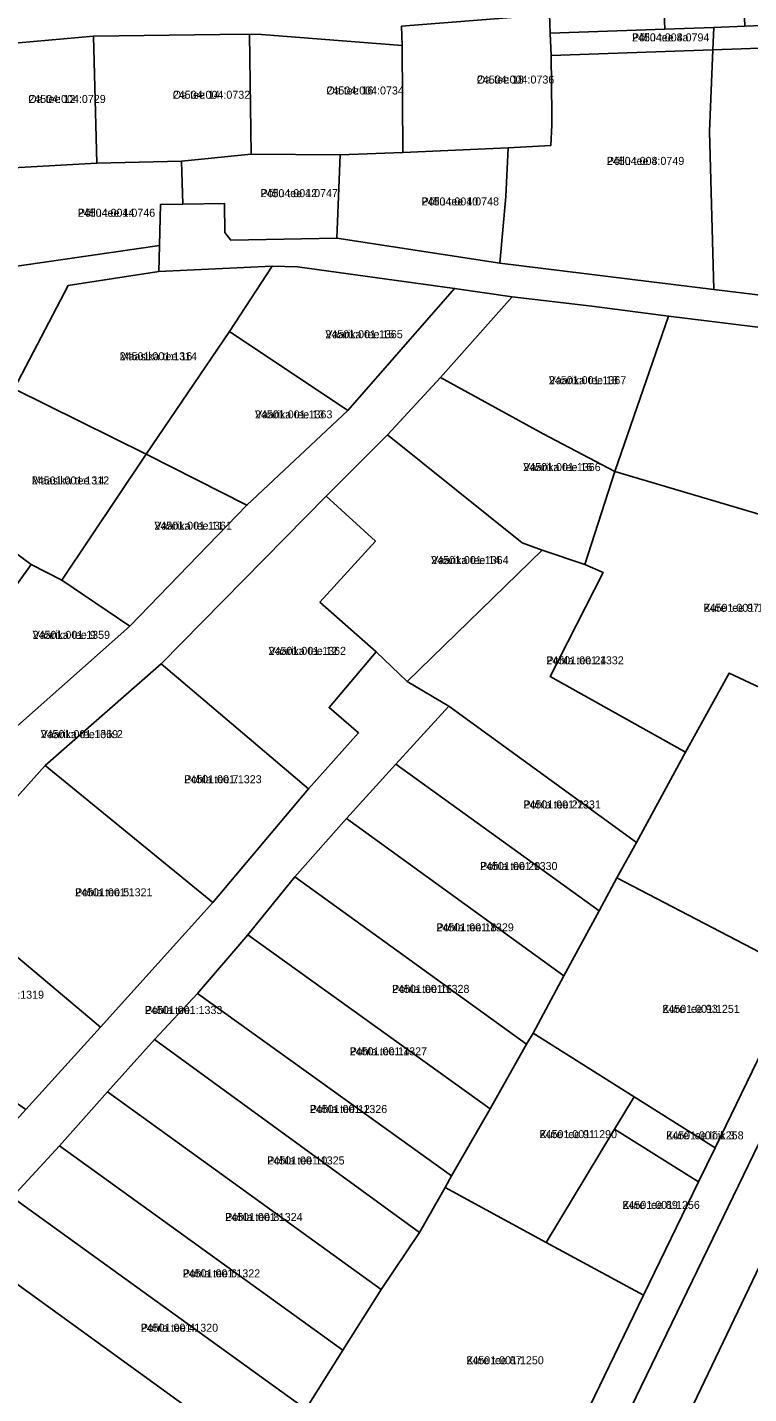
# Model space of a CAD drawing. Extents: x 551291 to 575799, y 6581704 to 6610137.
# Drawn here: x 559243.4 to 559378.6, y 6593957.3 to 6594213.3 of the extents above; entities that cross this region are included whole.
import ezdxf

# ---------------------------------------------------------------- set-up
doc = ezdxf.new("R2010")
doc.units = 0
for name, color, linetype in [('L_AADRESS', 7, 'Continuous'), ('PIIR', 7, 'Continuous'), ('TUNNUS', 7, 'Continuous')]:
    doc.layers.add(name, color=color, linetype=linetype)

msp = doc.modelspace()

# ---------------------------------------------------------------- linework, layer by layer
at = {"layer": 'PIIR'}
for points in [[(559360.98, 6594319.58), (559370.22, 6594319.03), (559371.34, 6594293.74), (559372.28, 6594272.9), (559373.15, 6594252.95), (559374, 6594233.72), (559374.56, 6594221.12), (559377.53, 6594221.22), (559377.81, 6594213.53), (559372.03, 6594213.32), (559362.82, 6594213), (559362.55, 6594220.7), (559365.37, 6594220.81), (559364.01, 6594251.33), (559363.11, 6594271.73), (559362.14, 6594293.49)], [(559339.71, 6594249.91), (559364.01, 6594251.33), (559365.37, 6594220.81), (559362.55, 6594220.7), (559362.82, 6594213), (559341.38, 6594212.26), (559341.23, 6594215.7)], [(559313.5, 6594213.53), (559341.23, 6594215.7), (559341.38, 6594212.26), (559341.57, 6594208.06), (559341.64, 6594197), (559341.67, 6594195.06), (559341.48, 6594191.17), (559333.49, 6594190.74), (559313.76, 6594189.88), (559313.6, 6594209.89)], [(559341.38, 6594212.26), (559362.82, 6594213), (559372.03, 6594213.32), (559371.86, 6594209.12), (559341.57, 6594208.06)], [(559372.03, 6594213.32), (559377.81, 6594213.53), (559390.9, 6594214.04), (559391.34, 6594209.8), (559371.86, 6594209.12)], [(559230.42, 6594209.43), (559255.79, 6594211.66), (559256.4, 6594187.84), (559240.77, 6594186.97), (559231.8, 6594186.64)], [(559255.79, 6594211.66), (559279.49, 6594211.99), (559285.04, 6594212.04), (559285.36, 6594189.56), (559272.3, 6594188.24), (559256.4, 6594187.84)], [(559285.04, 6594212.04), (559287.3, 6594211.98), (559313.6, 6594209.89), (559313.76, 6594189.88), (559302, 6594189.44), (559285.36, 6594189.56)], [(559341.57, 6594208.06), (559371.86, 6594209.12), (559371.19, 6594193.81), (559372.02, 6594164.2), (559331.93, 6594169.16), (559333.08, 6594181.65), (559333.49, 6594190.74), (559341.48, 6594191.17), (559341.67, 6594195.06), (559341.64, 6594197)], [(559371.86, 6594209.12), (559391.34, 6594209.8), (559396.5, 6594159.81), (559384.32, 6594162.68), (559372.02, 6594164.2), (559371.19, 6594193.81)], [(559272.3, 6594188.24), (559285.36, 6594189.56), (559302, 6594189.44), (559301.37, 6594173.82), (559281.5, 6594173.45), (559280.41, 6594174.89), (559280.31, 6594180.32), (559272.53, 6594180.18)], [(559302, 6594189.44), (559313.76, 6594189.88), (559333.49, 6594190.74), (559333.08, 6594181.65), (559331.93, 6594169.16), (559301.37, 6594173.82)], [(559240.77, 6594186.97), (559256.4, 6594187.84), (559272.3, 6594188.24), (559272.53, 6594180.18), (559268.32, 6594180.11), (559268.14, 6594172.42), (559233.63, 6594167.43)], [(559141.77, 6594022.54), (559133.39, 6594026.69), (559151.28, 6594046.35), (559186.46, 6594085.05), (559197.1, 6594096.92), (559217.09, 6594129.91), (559229.13, 6594155.42), (559233.63, 6594167.43), (559268.14, 6594172.42), (559268.03, 6594167.56), (559251.07, 6594164.93), (559240.92, 6594145.6), (559225.55, 6594126.37), (559210.74, 6594101.87), (559204.3, 6594091.2), (559175.94, 6594060.13)], [(559240.92, 6594145.6), (559251.07, 6594164.93), (559268.03, 6594167.56), (559289.26, 6594168.57), (559281.29, 6594156.31), (559265.69, 6594133.31)], [(559281.29, 6594156.31), (559289.26, 6594168.57), (559294.01, 6594168.44), (559323.46, 6594164.39), (559303.46, 6594141.55)], [(559176.16, 6593995.86), (559169.11, 6594001.47), (559187.62, 6594022.9), (559201.71, 6594038.84), (559219.93, 6594058.81), (559236.88, 6594077.64), (559240.46, 6594081.45), (559262.6, 6594101.09), (559284.55, 6594123.76), (559303.46, 6594141.55), (559323.46, 6594164.39), (559334.22, 6594162.81), (559320.79, 6594147.7), (559310.88, 6594136.93), (559299.37, 6594125.45), (559268.46, 6594094.04), (559246.72, 6594074.98), (559226.13, 6594052.02), (559209.61, 6594033.82), (559191.25, 6594013.56)], [(559320.79, 6594147.7), (559334.22, 6594162.81), (559349.19, 6594161.04), (559363.55, 6594159.21), (559353.48, 6594130.09), (559340.07, 6594137.15)], [(559353.48, 6594130.09), (559363.55, 6594159.21), (559383.32, 6594156.78), (559406.79, 6594151.23), (559396.8, 6594124.4), (559395.42, 6594117.64)], [(559265.69, 6594133.31), (559281.29, 6594156.31), (559303.46, 6594141.55), (559284.55, 6594123.76)], [(559310.88, 6594136.93), (559320.79, 6594147.7), (559340.07, 6594137.15), (559353.48, 6594130.09), (559347.84, 6594112.65), (559339.89, 6594115.33), (559336.09, 6594116.74)], [(559225.55, 6594126.37), (559240.92, 6594145.6), (559265.69, 6594133.31), (559249.84, 6594109.71), (559244.12, 6594112.66)], [(559171.21, 6593753.59), (559201.87, 6593775.34), (559209.55, 6593780.73), (559246.25, 6593806.94), (559271.02, 6593824.58), (559293.51, 6593840.52), (559316.24, 6593887.55), (559335.18, 6593926.77), (559358.82, 6593975.74), (559369.18, 6593996.97), (559372.27, 6594003.33), (559388.13, 6594036.07), (559408, 6594077.05), (559411.94, 6594085.21), (559438.12, 6594139.38), (559444.58, 6594136.67), (559299.06, 6593836.09), (559146.17, 6593723.99), (559138.1, 6593729.93)], [(559308.63, 6594117.03), (559299.37, 6594125.45), (559310.88, 6594136.93), (559336.09, 6594116.74), (559339.89, 6594115.33), (559314.57, 6594090.74), (559308.74, 6594096.28), (559298.23, 6594105.61)], [(559249.84, 6594109.71), (559265.69, 6594133.31), (559284.55, 6594123.76), (559262.6, 6594101.09)], [(559347.84, 6594112.65), (559353.48, 6594130.09), (559395.42, 6594117.64), (559390.93, 6594094.77), (559387.35, 6594086.49), (559374.9, 6594092.31), (559366.72, 6594077.52), (559341.33, 6594091.68), (559351.27, 6594111.15)], [(559210.74, 6594101.87), (559225.55, 6594126.37), (559244.12, 6594112.66), (559226.18, 6594087.74)], [(559296.09, 6594070.61), (559268.46, 6594094.04), (559299.37, 6594125.45), (559308.63, 6594117.03), (559298.23, 6594105.61), (559308.74, 6594096.28), (559299.94, 6594085.85), (559305.45, 6594081.11)], [(559322.35, 6594086.1), (559314.57, 6594090.74), (559339.89, 6594115.33), (559347.84, 6594112.65), (559351.27, 6594111.15), (559341.33, 6594091.68), (559366.72, 6594077.52), (559357.52, 6594060.57)], [(559236.88, 6594077.64), (559226.18, 6594087.74), (559244.12, 6594112.66), (559249.84, 6594109.71), (559262.6, 6594101.09), (559240.46, 6594081.45)], [(559216.33, 6593968.06), (559208.51, 6593972.88), (559228.04, 6593993.97), (559243.12, 6594010.55), (559257.11, 6594025.97), (559278.13, 6594049.31), (559296.09, 6594070.61), (559305.45, 6594081.11), (559299.94, 6594085.85), (559308.74, 6594096.28), (559314.57, 6594090.74), (559322.35, 6594086.1), (559312.44, 6594075.24), (559303.19, 6594065.05), (559293.53, 6594054.14), (559284.72, 6594043.28), (559275.28, 6594032.28), (559267.25, 6594023.67), (559258.44, 6594013.84), (559249.43, 6594003.75), (559240.57, 6593994.11), (559231.85, 6593984.75)], [(559278.13, 6594049.31), (559246.72, 6594074.98), (559268.46, 6594094.04), (559296.09, 6594070.61)], [(559366.72, 6594077.52), (559374.9, 6594092.31), (559387.35, 6594086.49), (559408, 6594077.05), (559388.13, 6594036.07), (559353.88, 6594053.95), (559357.52, 6594060.57)], [(559350.52, 6594047.77), (559312.44, 6594075.24), (559322.35, 6594086.1), (559357.52, 6594060.57), (559353.88, 6594053.95)], [(559257.11, 6594025.97), (559226.13, 6594052.02), (559246.72, 6594074.98), (559278.13, 6594049.31)], [(559343.93, 6594035.56), (559303.19, 6594065.05), (559312.44, 6594075.24), (559350.52, 6594047.77)], [(559336.9, 6594022.76), (559293.53, 6594054.14), (559303.19, 6594065.05), (559343.93, 6594035.56), (559338.17, 6594024.81)], [(559330.1, 6594010.63), (559284.72, 6594043.28), (559293.53, 6594054.14), (559336.9, 6594022.76)], [(559357.07, 6594012.9), (559338.17, 6594024.81), (559343.93, 6594035.56), (559350.52, 6594047.77), (559353.88, 6594053.95), (559388.13, 6594036.07), (559372.27, 6594003.33)], [(559243.12, 6594010.55), (559209.61, 6594033.82), (559226.13, 6594052.02), (559257.11, 6594025.97)], [(559322.9, 6593998.07), (559275.28, 6594032.28), (559284.72, 6594043.28), (559330.1, 6594010.63)], [(559316.9, 6593987.46), (559267.25, 6594023.67), (559275.28, 6594032.28), (559322.9, 6593998.07), (559321.68, 6593995.94)], [(559309.71, 6593976.78), (559258.44, 6594013.84), (559267.25, 6594023.67), (559316.9, 6593987.46)], [(559340.62, 6593985.59), (559321.68, 6593995.94), (559322.9, 6593998.07), (559330.1, 6594010.63), (559336.9, 6594022.76), (559338.17, 6594024.81), (559357.07, 6594012.9), (559353.42, 6594006.86)], [(559302.54, 6593965.43), (559249.43, 6594003.75), (559258.44, 6594013.84), (559309.71, 6593976.78)], [(559369.18, 6593996.97), (559353.42, 6594006.86), (559357.07, 6594012.9), (559372.27, 6594003.33)], [(559358.82, 6593975.74), (559340.62, 6593985.59), (559353.42, 6594006.86), (559369.18, 6593996.97)], [(559295.57, 6593954.38), (559240.57, 6593994.11), (559249.43, 6594003.75), (559302.54, 6593965.43)], [(559329.03, 6593930.04), (559292.49, 6593949.23), (559295.57, 6593954.38), (559302.54, 6593965.43), (559309.71, 6593976.78), (559316.9, 6593987.46), (559321.68, 6593995.94), (559340.62, 6593985.59), (559358.82, 6593975.74), (559335.18, 6593926.77)], [(559288.65, 6593943.64), (559231.85, 6593984.75), (559240.57, 6593994.11), (559295.57, 6593954.38), (559292.49, 6593949.23)], [(559356.41, 6593930.63), (559383.45, 6593987.17), (559409.15, 6593975.66), (559399.46, 6593951.77), (559396.72, 6593952.85), (559384.6, 6593929.42), (559377.88, 6593931.06), (559371.31, 6593922.02)], [(559216.48, 6593966.93), (559216.33, 6593968.06), (559231.85, 6593984.75), (559288.65, 6593943.64), (559277.28, 6593925.6)]]:
    msp.add_lwpolyline(points, close=True, dxfattribs=at)
for points in [[(559313.5, 6594213.53), (559313.6, 6594209.89), (559287.3, 6594211.98), (559285.04, 6594212.04), (559279.49, 6594211.99), (559255.79, 6594211.66), (559230.42, 6594209.43), (559203.44, 6594209.05), (559177.17, 6594208.65), (559147.66, 6594208.18), (559120.38, 6594207.76), (559108.39, 6594207.58), (559108.36, 6594209.68), (559108.17, 6594222.79)], [(558177.52, 6592770.55), (558170.99, 6592891.67), (558187.73, 6592959.33), (558210.3, 6593010.98), (558251.88, 6593067.47), (558331.23, 6593148.23), (558500.98, 6593273.8), (558515.98, 6593265.59), (558725.44, 6593417.8), (558892.15, 6593539.14), (558974.44, 6593599.03), (559131.4, 6593713.23), (559146.17, 6593723.99), (559299.06, 6593836.09), (559444.58, 6594136.67), (559447.22, 6594142.1), (559464.89, 6594178.58), (559481.53, 6594212.94), (559484.05, 6594218.05)], [(559492.26, 6594213.33), (559480.81, 6594189.47), (559468.99, 6594164.84), (559453.77, 6594133.23), (559441.92, 6594108.7), (559431.33, 6594086.6), (559425.5, 6594074.54), (559399.64, 6594020.83), (559383.45, 6593987.17), (559356.41, 6593930.63), (559317.89, 6593848.3), (559321.54, 6593844.35), (559395.22, 6593879.55), (559395, 6593880.5), (559407.84, 6593886.81), (559427.42, 6593891.23), (559444.52, 6593895.06), (559451.86, 6593896.71), (559469.1, 6593898.55), (559486.64, 6593900.44), (559517.17, 6593903.73), (559533.53, 6593905.49)], [(559383.32, 6594156.78), (559363.55, 6594159.21), (559349.19, 6594161.04), (559334.22, 6594162.81), (559323.46, 6594164.39), (559294.01, 6594168.44), (559289.26, 6594168.57), (559268.03, 6594167.56), (559268.14, 6594172.42), (559268.32, 6594180.11), (559272.53, 6594180.18), (559280.31, 6594180.32), (559280.41, 6594174.89), (559281.5, 6594173.45), (559301.37, 6594173.82), (559331.93, 6594169.16), (559372.02, 6594164.2), (559384.32, 6594162.68)]]:
    msp.add_lwpolyline(points, dxfattribs=at)

# ---------------------------------------------------------------- texts
at = {"layer": 'L_AADRESS'}
for s, p in [('Põllu tee 8a', (559356.69, 6594210.69)), ('Oa tee 16', (559299.44, 6594200.74)), ('Oa tee 18', (559327.63, 6594202.79)), ('Oa tee 12', (559243.58, 6594199.15)), ('Oa tee 14', (559270.65, 6594199.94)), ('Põllu tee 8', (559351.98, 6594187.55)), ('Põllu tee 12', (559287.09, 6594181.5)), ('Põllu tee 14', (559252.85, 6594177.83)), ('Põllu tee 10', (559317.27, 6594179.95)), ('Vaarika tee 15', (559299.23, 6594155.06)), ('Maasika tee 16', (559260.69, 6594150.94)), ('Vaarika tee 18', (559341.11, 6594146.45)), ('Vaarika tee 13', (559286.05, 6594140.04)), ('Vaarika tee 16', (559336.32, 6594130.17)), ('Maasika tee 14', (559244.23, 6594127.66)), ('Vaarika tee 11', (559267.2, 6594119.19)), ('Vaarika tee 14', (559319.06, 6594112.74)), ('Kure tee 97', (559370.11, 6594103.8)), ('Vaarika tee 9', (559244.39, 6594098.73)), ('Vaarika tee 12', (559288.6, 6594095.73)), ('Pohla tee 24', (559340.64, 6594093.95)), ('Vaarika tee lõik 2', (559245.9, 6594080.12)), ('Pohla tee 7', (559272.8, 6594071.67)), ('Pohla tee 22', (559336.35, 6594066.94)), ('Pohla tee 20', (559328.23, 6594055.4)), ('Pohla tee 5', (559252.34, 6594050.48)), ('Pohla tee 18', (559320.04, 6594043.91)), ('Pohla tee 16', (559311.73, 6594032.38)), ('Pohla tee', (559265.43, 6594028.42)), ('Kure tee 93', (559362.38, 6594028.64)), ('Pohla tee 14', (559303.79, 6594020.68)), ('Pohla tee 12', (559296.32, 6594009.87)), ('Kure tee 91', (559339.38, 6594005.16)), ('Kure tee lõik 3', (559363.1, 6594004.93)), ('Pohla tee 10', (559288.34, 6594000.23)), ('Kure tee 89', (559354.9, 6593991.9)), ('Pohla tee 8', (559280.46, 6593989.63)), ('Pohla tee 6', (559272.52, 6593979.07)), ('Pohla tee 4', (559264.64, 6593968.88)), ('Kure tee 87', (559325.66, 6593962.79))]:
    msp.add_text(s, height=1.5, dxfattribs=at).set_placement(p)
at = {"layer": 'TUNNUS'}
for s, p in [('24504:004:0794', (559356.69, 6594210.69)), ('24504:004:0734', (559299.44, 6594200.74)), ('24504:004:0736', (559327.63, 6594202.79)), ('24504:004:0729', (559243.58, 6594199.15)), ('24504:004:0732', (559270.65, 6594199.94)), ('24504:004:0749', (559351.98, 6594187.55)), ('24504:004:0747', (559287.09, 6594181.5)), ('24504:004:0746', (559252.85, 6594177.83)), ('24504:004:0748', (559317.27, 6594179.95)), ('24501:001:1365', (559299.23, 6594155.06)), ('24501:001:1314', (559260.69, 6594150.94)), ('24501:001:1367', (559341.11, 6594146.45)), ('24501:001:1363', (559286.05, 6594140.04)), ('24501:001:1366', (559336.32, 6594130.17)), ('24501:001:1312', (559244.23, 6594127.66)), ('24501:001:1361', (559267.2, 6594119.19)), ('24501:001:1364', (559319.06, 6594112.74)), ('24501:001:1253', (559370.11, 6594103.8)), ('24501:001:1359', (559244.39, 6594098.73)), ('24501:001:1362', (559288.6, 6594095.73)), ('24501:001:1332', (559340.64, 6594093.95)), ('24501:001:1369', (559245.9, 6594080.12)), ('24501:001:1323', (559272.8, 6594071.67)), ('24501:001:1331', (559336.35, 6594066.94)), ('24501:001:1330', (559328.23, 6594055.4)), ('24501:001:1321', (559252.34, 6594050.48)), ('24501:001:1329', (559320.04, 6594043.91)), ('24501:001:1328', (559311.73, 6594032.38)), ('24501:001:1319', (559232.02, 6594031.29)), ('24501:001:1333', (559265.43, 6594028.42)), ('24501:001:1251', (559362.38, 6594028.64)), ('24501:001:1327', (559303.79, 6594020.68)), ('24501:001:1326', (559296.32, 6594009.87)), ('24501:001:1290', (559339.38, 6594005.16)), ('24501:001:1258', (559363.1, 6594004.93)), ('24501:001:1325', (559288.34, 6594000.23)), ('24501:001:1256', (559354.9, 6593991.9)), ('24501:001:1324', (559280.46, 6593989.63)), ('24501:001:1322', (559272.52, 6593979.07)), ('24501:001:1320', (559264.64, 6593968.88)), ('24501:001:1250', (559325.66, 6593962.79))]:
    msp.add_text(s, height=1.5, dxfattribs=at).set_placement(p)

doc.saveas('drawing.dxf')
